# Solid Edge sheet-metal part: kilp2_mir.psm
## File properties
Author: Kasutaja
Template: Ansi Inch Sheet Metal.psm
Last saved by: Kasutaja
Revision: 2
Application: Solid Edge
Accuracy: 0,990
Material Thickness: 0,079 in
Bend Radius: 0,039 in
Relief Width: 0,039 in
Relief Length: 0,000 in
Neutral Factor: 0,330
Minimum Arc Length: 0,005 in
Deviational Tolerance: 0,005 in
Username: Kasutaja
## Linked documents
kilp2.psm
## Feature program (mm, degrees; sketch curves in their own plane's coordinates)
part copy "CopiedPart_1"
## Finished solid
Body 1: solid body, 86 faces, 168 edges, 84 vertices.
  Faces by surface: plane 50, cylinder 14, spline 12, torus 6, cone 4
  Edges by curve: line 114, circle 30, curve on surface 24
Bounding box of the edges (mm; curved faces can reach further): 72.568 x 12.000 x 64.041, from (-36.284, -5, -32.0205) to (36.284, 7, 32.0205).
Cylindrical faces by radius (mm): R1 x6, R3 x6, R5.5 x1, R7.5 x1
Conical faces (half-angle, radius in mm at the cone's reference point): 15 deg R15.9605 x1, 15 deg R17.8924 x1, 15 deg R21.1028 x1, 15 deg R23.0347 x1
Toroidal faces (ring radius, tube radius in mm): R5.5 r2 x1, R7.5 r2 x1, R15.9605 r2 x1, R18.5 r2 x1, R21.5 r2 x1, R24.0395 r2 x1
Planar faces by outward normal: +y 10, -y 10, oblique 30
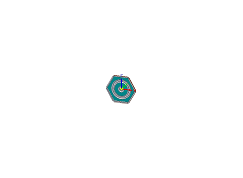
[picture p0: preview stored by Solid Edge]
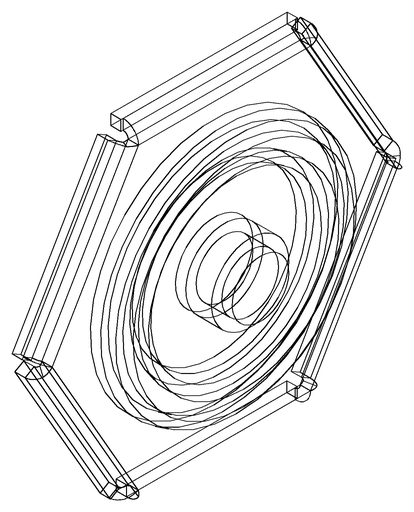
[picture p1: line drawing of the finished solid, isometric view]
